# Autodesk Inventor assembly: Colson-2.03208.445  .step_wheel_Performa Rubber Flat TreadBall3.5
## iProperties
Created: 2010-10
Part Number: Colson-2.03208.445  .step_wheel_Performa Rubber Flat TreadBall3.5
Document SubType Name: Assembly
Designer: Administrator
Mass: 248.42 g
Surface Area: 409.073 cm^2
Volume: 154.86 cm^3
Density: 1.60416 g/cm^3
Author: Administrator
